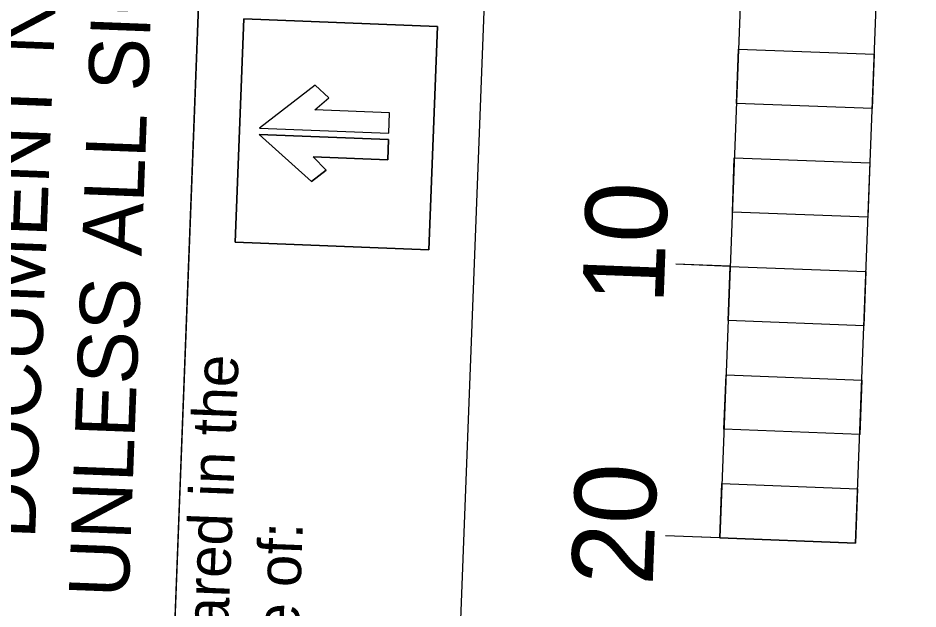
# Model space of a CAD drawing. Extents: x 2097521 to 2097987, y 686521 to 687299.
# Drawn here: x 2097612.75 to 2097645.89, y 687127.59 to 687149.33 of the extents above; entities that cross this region are included whole.
import ezdxf

# ---------------------------------------------------------------- set-up
doc = ezdxf.new("R2010")
doc.units = 0
for name, color, linetype in [('Sheet Block Title CELL', 7, 'Continuous'), ('Sheet Data Field CELL', 7, 'Continuous'), ('Sheet Sticker Exception Certification CELL', 7, 'Continuous'), ('Sheet Title CELL', 7, 'Continuous')]:
    doc.layers.add(name, color=color, linetype=linetype)

msp = doc.modelspace()

# ---------------------------------------------------------------- linework, layer by layer
at = {"layer": 'Sheet Block Title CELL'}
for points in [[(2097618.314, 687121.52), (2097621.38, 687201.485), (2097631.875, 687201.082), (2097628.808, 687121.118)], [(2097620.748, 687141.083), (2097621.063, 687149.3), (2097628.195, 687149.026), (2097627.88, 687140.809)], [(2097621.639, 687145.283), (2097626.408, 687145.1), (2097626.437, 687145.851), (2097623.686, 687145.957), (2097624.197, 687146.403), (2097623.691, 687146.861)]]:
    msp.add_lwpolyline(points, close=True, dxfattribs=at)
for points in [[(2097621.063, 687149.3), (2097620.748, 687141.083), (2097627.88, 687140.809), (2097628.195, 687149.026), (2097621.063, 687149.3)], [(2097621.639, 687145.283), (2097626.408, 687145.1), (2097626.437, 687145.851), (2097623.686, 687145.957), (2097624.197, 687146.403), (2097623.691, 687146.861), (2097621.639, 687145.283)], [(2097621.631, 687145.052), (2097626.399, 687144.869), (2097626.37, 687144.118), (2097623.62, 687144.223), (2097624.094, 687143.739), (2097623.555, 687143.322), (2097621.631, 687145.052)], [(2097623.555, 687143.322), (2097624.094, 687143.739), (2097623.62, 687144.223), (2097626.37, 687144.118), (2097626.399, 687144.869), (2097621.631, 687145.052), (2097623.555, 687143.322)]]:
    msp.add_lwpolyline(points, dxfattribs=at)
at = {"layer": 'Sheet Data Field CELL'}
for p, q in [((2097638.973, 687140.202), (2097636.974, 687140.279)), ((2097638.584, 687130.21), (2097636.591, 687130.286))]:
    msp.add_line(p, q, dxfattribs=at)
at = {"layer": 'Sheet Sticker Exception Certification CELL'}
msp.add_line((2097621.38, 687201.477), (2097618.314, 687121.52), dxfattribs=at)
at = {"layer": 'Sheet Title CELL'}
for p, q in [((2097640.889, 687190.161), (2097638.589, 687130.205)), ((2097643.586, 687130.013), (2097645.89, 687189.969)), ((2097639.126, 687144.195), (2097644.122, 687144.003)), ((2097638.978, 687140.197), (2097636.974, 687140.274)), ((2097638.589, 687130.205), (2097636.596, 687130.281)), ((2097636.596, 687130.281), (2097636.596, 687130.281)), ((2097638.589, 687130.205), (2097643.586, 687130.013)), ((2097638.589, 687130.205), (2097638.589, 687130.205))]:
    msp.add_line(p, q, dxfattribs=at)
for points in [[(2097639.202, 687146.193), (2097639.279, 687148.192), (2097644.28, 687148), (2097644.199, 687146.001)], [(2097639.054, 687142.196), (2097639.126, 687144.195), (2097644.122, 687144.003), (2097644.046, 687142.004)], [(2097638.901, 687138.199), (2097638.978, 687140.197), (2097643.969, 687140.006), (2097643.892, 687138.007)], [(2097638.743, 687134.202), (2097638.824, 687136.2), (2097643.821, 687136.009), (2097643.744, 687134.015)], [(2097638.589, 687130.205), (2097638.666, 687132.203), (2097643.662, 687132.012), (2097643.586, 687130.013)]]:
    msp.add_lwpolyline(points, close=True, dxfattribs=at)

# ---------------------------------------------------------------- texts
at = {"layer": 'Sheet Block Title CELL'}
for s, height, p in [('Prepared in the ', 1.60046, (2097620.318, 687122.293)), ('Office of:', 1.6005, (2097622.917, 687122.193))]:
    msp.add_text(s, height=height, rotation=87.8037, dxfattribs=at).set_placement(p)
at = {"layer": 'Sheet Data Field CELL'}
for s, p in [('10', (2097636.516, 687138.782)), ('20', (2097636.119, 687128.43))]:
    msp.add_text(s, height=3, rotation=87.8037, dxfattribs=at).set_placement(p)
at = {"layer": 'Sheet Sticker Exception Certification CELL'}
for s, p in [('UNLESS ALL SIGNATURES COMPLETED', (2097616.818, 687127.982)), ('DOCUMENT NOT CONSIDERED FINAL', (2097613.379, 687130.144))]:
    msp.add_text(s, height=2.2, rotation=87.8037, dxfattribs=at).set_placement(p)

doc.saveas('drawing.dxf')
